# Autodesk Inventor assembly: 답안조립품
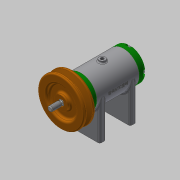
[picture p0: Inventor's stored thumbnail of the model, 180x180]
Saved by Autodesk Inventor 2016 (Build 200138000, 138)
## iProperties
Created: 2020-07
Part Number: 답안조립품
Document SubType Name: Assembly
Designer: user
Author: user
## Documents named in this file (12)
- C:\Users\user\Desktop\700706V1003\답안조립품.iam
- C:\Users\user\Desktop\700706V1003\본체.ipt
- C:\Users\user\Desktop\700706V1003\뒤커버.ipt
- C:\Users\user\Desktop\700706V1003\앞커버.ipt
- C:\Users\user\Desktop\700706V1003\축.ipt
- C:\Users\user\Desktop\700706V1003\키 3x3x12.ipt
- C:\Users\user\Desktop\700706V1003\베어링 6002.ipt
- C:\Users\user\Desktop\700706V1003\오일 실 15 25 7.ipt
- C:\Users\user\Desktop\700706V1003\볼트 M4x12.ipt
- C:\Users\user\Desktop\700706V1003\와셔 6x11.5.ipt
- C:\Users\user\Desktop\700706V1003\볼트 M6x8.ipt
- C:\Users\user\Desktop\700706V1003\V벨트풀리.ipt
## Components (1 placed, 1 different names)
1. V벨트풀리:1
